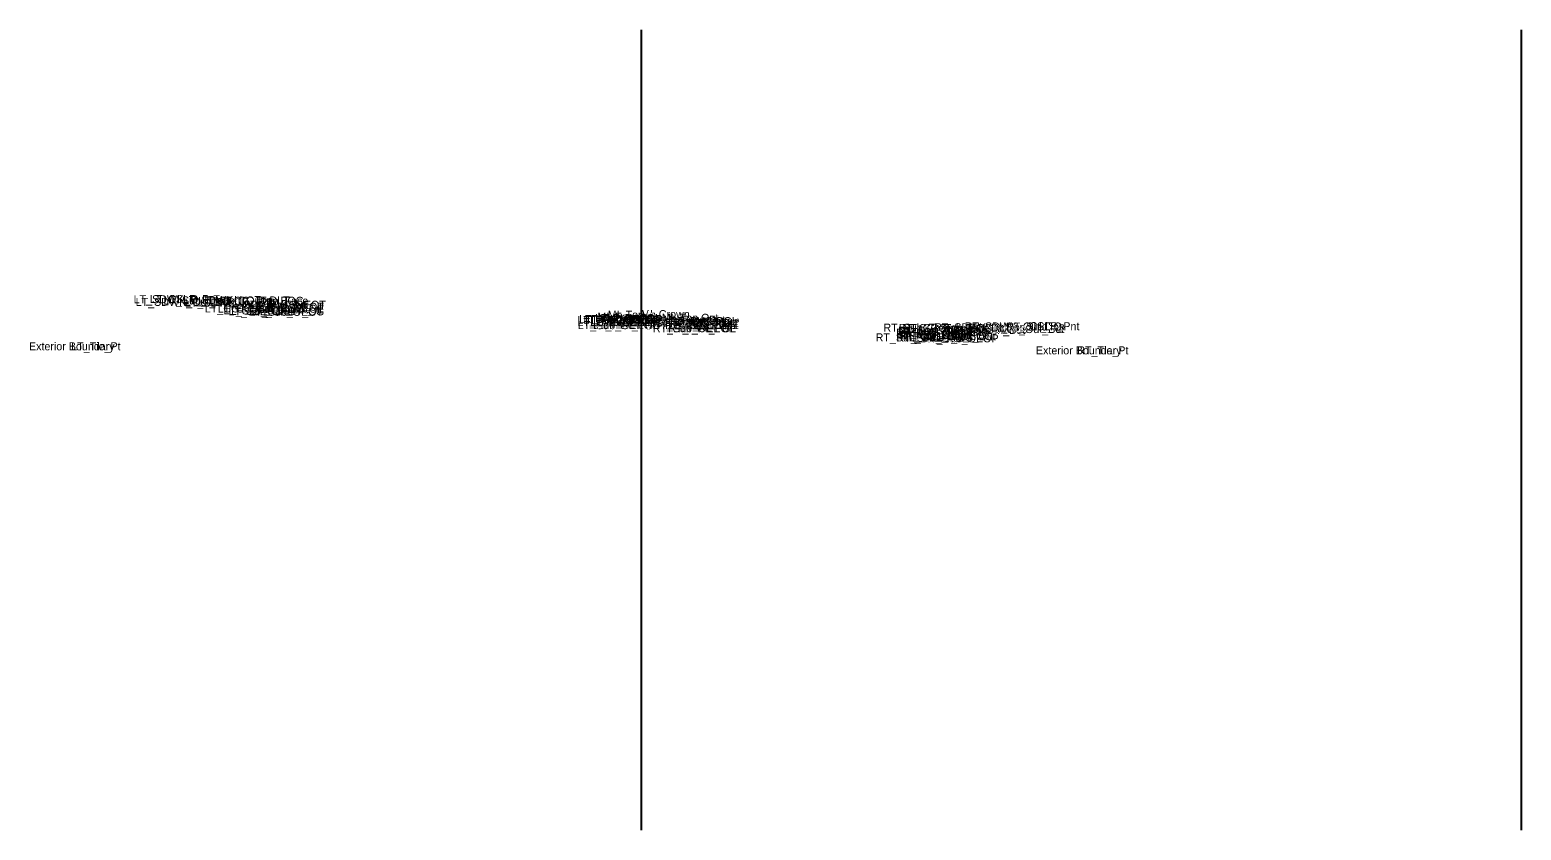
# Model space of a CAD drawing. Extents: x 0 to 6300, y -50 to 9550.
# Drawn here: x 1073.6 to 1260, y 4950 to 5050 of the extents above; entities that cross this region are included whole.
import ezdxf

# ---------------------------------------------------------------- set-up
doc = ezdxf.new("R2010")
doc.units = 0
for name, color, linetype in [('Default', 7, 'Continuous'), ('Prop XS Exc Vertical Line 2', 7, 'Continuous'), ('Prop XS Exc Vertical Line 3', 7, 'Continuous')]:
    doc.layers.add(name, color=color, linetype=linetype)

msp = doc.modelspace()

# ---------------------------------------------------------------- linework, layer by layer
at = {"layer": 'Prop XS Exc Vertical Line 2'}
msp.add_line((1150, 5050), (1150, 4950), dxfattribs=at)
at = {"layer": 'Prop XS Exc Vertical Line 3'}
msp.add_line((1260, 5050), (1260, 4950), dxfattribs=at)

# ---------------------------------------------------------------- texts
at = {"layer": 'Default'}
for s, p in [('LT_SDWK_Out_Top', (1086.58, 5015.84)), ('LT_SDWK_Out_Bot', (1086.83, 5015.51)), ('LT_CSLP_Pnt', (1088.6, 5015.87)), ('LT_Sub_Trench_Out_DLT', (1090.32, 5015.69)), ('LT_SDWK_In_Top', (1092.74, 5015.74)), ('LT_SDWK_In_Bot', (1092.99, 5015.41)), ('LT_CG_Top_BOC', (1096.81, 5015.65)), ('LT_CG_Top_Face', (1097.34, 5015.65)), ('LT_CG_Top_Gut', (1097.87, 5015.15)), ('LT_PV2_OEOT', (1100.99, 5014.9)), ('LT_PV1_OEOT', (1101.23, 5015.15)), ('LT_CG1_Shelf_Out', (1095.48, 5014.69)), ('LT_CG_Bot_BOC', (1097.09, 5014.67)), ('LT_Sub_OEOP', (1097.79, 5014.45)), ('LT_Sub_OEOT_CG', (1098.44, 5014.32)), ('LT_PV3_OEOT', (1100.99, 5014.65)), ('LT_Sub_OEOT', (1101.04, 5014.27)), ('LT_CG_Bot_IE', (1101.34, 5014.57)), ('LT_PV2_OEEOP', (1142.04, 5013.23)), ('LT_PV3_OEEOP', (1142.04, 5012.98)), ('LT_PV1_OEEOP', (1142.27, 5013.35)), ('LT_PV2_IEEOP', (1142.8, 5013.23)), ('LT_PV1_IEEOP', (1143.04, 5013.35)), ('LT_PV2_PGL1', (1143.63, 5013.23)), ('LT_PV3_PGL1', (1143.63, 5012.98)), ('LT_PV2_PGL', (1144.01, 5013.23)), ('LT_PV1_PGL', (1144.25, 5013.48)), ('MI_Face In', (1144.55, 5013.65)), ('MI_Bot In', (1145.72, 5013.48)), ('MI_Top In', (1145.84, 5013.9)), ('MI_Crown', (1149.99, 5013.98)), ('RT_PV1_OEEOP', (1151.66, 5012.97)), ('RT_PV1_IEEOP', (1152.42, 5012.97)), ('MI_Top Out', (1152.6, 5013.52)), ('MI_Face Out', (1152.81, 5013.27)), ('RT_PV1_PGL', (1153.63, 5013.1)), ('MI_Bot Out', (1154, 5013.1)), ('LT_Sub_OEEOP', (1142.08, 5012.6)), ('LT_PV4_PGL', (1144.01, 5012.6)), ('RT_PV2_OEEOP', (1151.42, 5012.85)), ('RT_PV3_OEEOP', (1151.42, 5012.6)), ('RT_Sub_OEEOP', (1151.46, 5012.22)), ('RT_PV2_IEEOP', (1152.18, 5012.85)), ('RT_PV2_PGL1', (1153.02, 5012.85)), ('RT_PV3_PGL1', (1153.02, 5012.6)), ('RT_PV2_PGL', (1153.4, 5012.85)), ('RT_PV4_PGL', (1153.4, 5012.22)), ('RT_Sub_OEOT_CG', (1179.32, 5011.08)), ('RT_Sub_Trench_Out_DLT', (1180.29, 5012.29)), ('RT_PV2_OEOT', (1181.87, 5011.66)), ('RT_PV3_OEOT', (1181.87, 5011.41)), ('RT_PV1_OEOT', (1182.11, 5011.91)), ('RT_CG_Top_Face', (1182.22, 5012.25)), ('RT_CG_Bot_IE', (1182.22, 5011.33)), ('RT_CG1_Shelf_Out', (1182.36, 5011.21)), ('RT_CG_Top_BOC', (1182.69, 5012.25)), ('RT_CG_Top_Gut', (1182.75, 5011.75)), ('RT_CG_Bot_BOC', (1182.97, 5011.23)), ('RT_SDWK_In_Top', (1186.62, 5012.34)), ('RT_SDWK_In_Bot', (1186.87, 5012.01)), ('RT_SDWK_Out_Top', (1190.46, 5012.44)), ('RT_SDWK_Out_Bot', (1190.71, 5012.11)), ('RT_Shld_O', (1195.63, 5012.43)), ('CSLP_Pnt', (1198.54, 5012.47)), ('Exterior Boundary', (1073.5, 5009.96)), ('LT_Tie_Pt', (1078.78, 5009.96)), ('RT_Sub_OEOT', (1181.92, 5011.03)), ('RT_Sub_OEOP', (1185.17, 5010.95)), ('Exterior Boundary', (1199.35, 5009.45)), ('RT_Tie_Pt', (1204.52, 5009.45))]:
    msp.add_text(s, height=1, dxfattribs=at).set_placement(p)

doc.saveas('drawing.dxf')
